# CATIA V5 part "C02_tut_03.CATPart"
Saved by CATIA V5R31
Part number: C02tut3
Bounding box of the stored display mesh (mm): x 0 to 0, y -40 to 40, z -30 to 30
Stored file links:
  D:\PROJECTS\Project 2021\US EDITION\CATIA V5 6R 2021\Resources\Tutorial Files\c02_catia_v5_6r2021_tut\C02_tut_03.CATPart
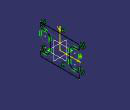
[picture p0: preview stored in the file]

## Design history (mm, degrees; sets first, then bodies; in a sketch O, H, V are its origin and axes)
Body1 (main body)
  Sketch1 on yz-plane, origin (0, 0, 0), H (0, 1, 0), V (0, 0, 1)
    line L1 (-40, -30) -> (40, -30)
    line L2 (40, -30) -> (40, -20)
    line L3 (40, -20) -> (30, -20)
    arc A1 centre (30, -10) radius 10 from (30, -20) to (20, -10) cw
    line L4 (20, -10) -> (20, 10)
    arc A2 centre (30, 10) radius 10 from (20, 10) to (30, 20) cw
    line L5 (30, 20) -> (40, 20)
    point P10 (40, 20)
    line L6 (40, 20) -> (40, 30)
    line L7 (40, 30) -> (-40, 30)
    line L8 (-40, 30) -> (-40, 20)
    point P13 (-40, 20)
    line L9 (-40, 20) -> (-30, 20)
    arc A3 centre (-30, 10) radius 10 from (-30, 20) to (-20, 10) cw
    line L10 (-20, 10) -> (-20, -10)
    arc A4 centre (-30, -10) radius 10 from (-20, -10) to (-30, -20) cw
    line L11 (-30, -20) -> (-40, -20)
    point P20 (-40, -20)
    line L12 (-40, -20) -> (-40, -30)
    horizontal: L1 H, L3 H, L7 H
    vertical: L2 V, L6 V, L8 V, L12 V
    tangency: A1 L3, L4 A1, A2 L2, A2 L4, L5 A2, L9 A2, A3 L8, A3 L9, L10 A3, A4 L3, A4 L10, L11 A4
    coincidence: P10 L2, P13 L5, P20 L8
